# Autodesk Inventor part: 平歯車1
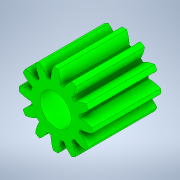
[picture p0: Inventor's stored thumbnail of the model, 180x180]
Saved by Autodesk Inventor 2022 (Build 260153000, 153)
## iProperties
CustomPartVersion: 1
Created: 2024-12
Part Number: 平歯車1
Material: Steel
Document SubType Name: Modeling
Designer: jsat7
Categories: <?xml version="1.0" encoding="UTF-16"?> <MemberInstance><Categories><FamilyTemplate><FamilyTemplateParameter ValueType="xs:double" Id="1" ObjectReferenceKey="da
Density: 1 g/cm^3
Appearance: Steel
Author: jsat7
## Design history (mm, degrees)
sketch "Sketch1"
  geometry: C1 r 3.5 at (0, 0)
  constraints: 1 centre point
  dimensions: "d0" = 7 diameter of C1 (= da_da)
extrude "Extrusion1" new body sketch "Sketch1" distance "d1" = 6.6 (= da_b); taper "d2" = 0 deg
workplane "Work Plane2"
sketch "Sketch2"
  geometry: C1 r 3.5 at (0, 0) reference; C2 r 3 at (0, 0)
  constraints: 1 centre point, 1 coincident
  dimensions: "d3" = 6 diameter of C2 (= da_d)
feature "ピッチ円直径" sketch "Sketch2" dims "d4" = 10, "d5" = 0
workplane "Work Plane8"
workplane "Work Plane9"
feature "平歯車" dims "d4" = 10, "da_b" = 6.6, "da_d" = 6, "da_aw" = 11.25, "da_da" = 7, "da_df" = 4.75, "da_dw" = 6, angle "da_beta" = 0 deg, "da_lefttooth" = 0, "da_righttooth" = 0
sketch "スケッチ3"
  geometry: C1 r 1.5 at (0, 0); 1 further point
  constraints: 1 centre point, 1 coincident
  dimensions: "d49" = 3 diameter of C1
extrude "押し出し2" cut sketch "スケッチ3" distance "d50" = 10; taper "d51" = 0 deg
body "Solid1"
body "Srf1"
other parameters: "d16" = 11.25 (= da_aw), "d17" = 0, "d34" = 15 deg (computed from da_z), "d39" = 0, "d41" = 0, "d43" = 11.25 (= da_aw), "d46" = 11.25 (= da_aw), "d47" = 0, "d48" = 0
